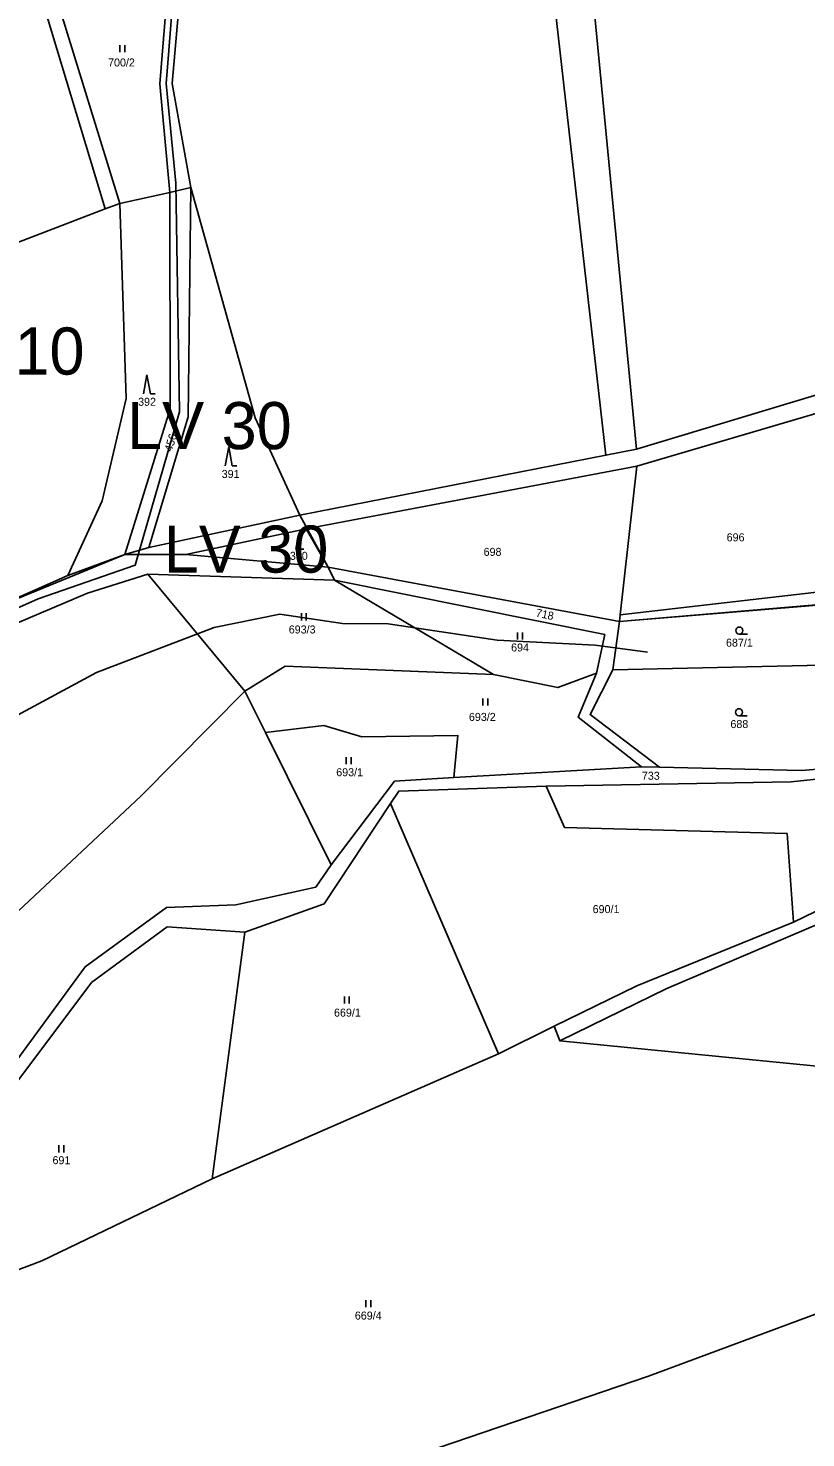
# Model space of a CAD drawing. Extents: x -590606 to -587796, y -1065936 to -1062515.
# Drawn here: x -589979.7 to -589814.6, y -1064835.5 to -1064536.2 of the extents above; entities that cross this region are included whole.
import ezdxf

# ---------------------------------------------------------------- set-up
doc = ezdxf.new("R2010")
doc.units = 0
for name, color, linetype in [('Cesty', 7, 'Continuous'), ('Lesy', 7, 'Continuous'), ('Parcela nároku', 7, 'Continuous'), ('Plocha pro ocenění', 7, 'Continuous'), ('Tok', 7, 'Continuous'), ('Vnější obvod_ Studené', 7, 'Continuous'), ('Vrstva 30', 7, 'Continuous'), ('Čísla LV', 7, 'Continuous')]:
    doc.layers.add(name, color=color, linetype=linetype)

msp = doc.modelspace()

# ---------------------------------------------------------------- linework, layer by layer
at = {"layer": 'Cesty'}
msp.add_lwpolyline([(-589947.72, -1064513.59), (-589949.88, -1064540.92), (-589950.43, -1064547.89), (-589948.41, -1064569.06), (-589947.59, -1064617.66), (-589957.04, -1064650.23), (-589977.62, -1064657.4), (-589994.52, -1064664.89), (-590000.93, -1064670.22), (-590029.62, -1064701.27), (-590052.7, -1064729.41), (-590072.54, -1064740.91), (-590082.04, -1064743), (-590136.41, -1064743.6)], dxfattribs=at)
at = {"layer": 'Lesy'}
for points in [[(-589945.2, -1064570.03), (-589931.51, -1064618.95), (-589922.06, -1064639.58), (-589954.11, -1064646.46), (-589945.75, -1064618.69)], [(-589946.23, -1064647.93), (-589920.74, -1064642.49), (-589916.03, -1064650.62)]]:
    msp.add_lwpolyline(points, close=True, dxfattribs=at)
at = {"layer": 'Parcela nároku'}
for points in [[(-589880.45, -1064400.57), (-589883.7, -1064393.06), (-589937.59, -1064438.88), (-590003.8, -1064511.09), (-590053.49, -1064555.03), (-590124.11, -1064592.68), (-590124.92, -1064590.99), (-590186.83, -1064622.39), (-590180.83, -1064633.16), (-590150.37, -1064687.39), (-590126.23, -1064681.5), (-590102.55, -1064674.49), (-590052.75, -1064654.76), (-590044.76, -1064645), (-590019.81, -1064609.39), (-590007.04, -1064591.31), (-589963.4, -1064574.51), (-589977.74, -1064526.91), (-589976.91, -1064516.68), (-589967.81, -1064501.82), (-589959.93, -1064493.53), (-589948.84, -1064472.81), (-589924.19, -1064439.77), (-589897.81, -1064414.93)], [(-589967.81, -1064501.82), (-589959.93, -1064493.53), (-589948.84, -1064472.81), (-589924.19, -1064439.77), (-589897.81, -1064414.93), (-589880.45, -1064400.57), (-589906.36, -1064425.79), (-589923.6, -1064442.15), (-589947.44, -1064475.52), (-589957.82, -1064495.76), (-589967.27, -1064504.99), (-589974.01, -1064517.56), (-589974.3, -1064527.88), (-589960.29, -1064573.39), (-589963.4, -1064574.51), (-589977.74, -1064526.91), (-589976.91, -1064516.68)], [(-589926.55, -1064452.59), (-589940.54, -1064479.13), (-589948.85, -1064511.85), (-589950.26, -1064528.81), (-589951.76, -1064548.03), (-589949.66, -1064571.06), (-589945.2, -1064570.03), (-589949.14, -1064547.91), (-589946.2, -1064514.04), (-589938.56, -1064481.34), (-589924.47, -1064455.4), (-589901.32, -1064431.9), (-589880.8, -1064419.92), (-589872.2, -1064414.96), (-589874.07, -1064412.43), (-589903.34, -1064429.38)], [(-589859.55, -1064532.21), (-589850.56, -1064625.55), (-589857.07, -1064626.89), (-589868.73, -1064524.47), (-589880.8, -1064419.92), (-589872.2, -1064414.96), (-589869.39, -1064418.76), (-589870.68, -1064462.95), (-589866.7, -1064505.87)], [(-589857.07, -1064626.89), (-589868.73, -1064524.47), (-589880.8, -1064419.92), (-589901.32, -1064431.9), (-589924.47, -1064455.4), (-589938.56, -1064481.34), (-589946.2, -1064514.04), (-589949.14, -1064547.91), (-589945.2, -1064570.03), (-589931.51, -1064618.95), (-589922.06, -1064639.58)], [(-589813.71, -1064476.97), (-589812.63, -1064521.48), (-589808.25, -1064610.3), (-589808.34, -1064612.83), (-589850.56, -1064625.55), (-589859.55, -1064532.21), (-589866.7, -1064505.87), (-589870.68, -1064462.95), (-589869.39, -1064418.76), (-589851.16, -1064443.43), (-589836.69, -1064459.05), (-589820.49, -1064473.59)], [(-589951.76, -1064548.03), (-589949.66, -1064571.06), (-589960.29, -1064573.39), (-589974.3, -1064527.88), (-589950.26, -1064528.81)], [(-589949.56, -1064617.03), (-589959.2, -1064647.94), (-589954.11, -1064646.46), (-589945.75, -1064618.69), (-589945.2, -1064570.03), (-589949.66, -1064571.06)], [(-589922.06, -1064639.58), (-589931.51, -1064618.95), (-589945.2, -1064570.03), (-589945.75, -1064618.69), (-589954.11, -1064646.46)], [(-589964.01, -1064636.55), (-589958.96, -1064614.81), (-589960.29, -1064573.39), (-589949.66, -1064571.06), (-589949.56, -1064617.03), (-589959.2, -1064647.94), (-589971.3, -1064652.42)], [(-589958.96, -1064614.81), (-589960.29, -1064573.39), (-589963.4, -1064574.51), (-590007.04, -1064591.31), (-590019.81, -1064609.39), (-589987.38, -1064659.47), (-589971.3, -1064652.42), (-589964.01, -1064636.55)], [(-589812.35, -1064637.06), (-589807.43, -1064655.35), (-589854.05, -1064660.75), (-589850.49, -1064629.2), (-589810.83, -1064617.52)], [(-589920.74, -1064642.49), (-589850.49, -1064629.2), (-589854.05, -1064660.75), (-589854.21, -1064662.15), (-589916.03, -1064650.62)], [(-589920.74, -1064642.49), (-589946.23, -1064647.93), (-589916.03, -1064650.62)], [(-589854.21, -1064662.15), (-589916.03, -1064650.62), (-589914.7, -1064653.41), (-589857.33, -1064664.94), (-589859.04, -1064673.14), (-589862.93, -1064682.5), (-589849.55, -1064693.06), (-589845.68, -1064693.13), (-589860.43, -1064681.93), (-589855.58, -1064672.44)], [(-590029.38, -1064789.34), (-590030.32, -1064781.93), (-590026.74, -1064766.14), (-590014.61, -1064753.36), (-589994.33, -1064735.3), (-589955.82, -1064699.26), (-589933.74, -1064676.94), (-589954.36, -1064652.15), (-589967.17, -1064656.15), (-589994.87, -1064667.89), (-590049.73, -1064728.85)], [(-589880.93, -1064673.46), (-589914.7, -1064653.41), (-589954.36, -1064652.15), (-589933.74, -1064676.94), (-589925.19, -1064671.68)], [(-589914.7, -1064653.41), (-589857.33, -1064664.94), (-589859.04, -1064673.14), (-589867.3, -1064676.2), (-589880.93, -1064673.46)], [(-589807.43, -1064655.35), (-589854.05, -1064660.75), (-589854.21, -1064662.15), (-589806.62, -1064658.16), (-589803.11, -1064657.97), (-589803.58, -1064654.81)], [(-589855.58, -1064672.44), (-589854.21, -1064662.15), (-589806.62, -1064658.16), (-589803.11, -1064657.97), (-589802.35, -1064663.1), (-589801.71, -1064671.23)], [(-589925.19, -1064671.68), (-589880.93, -1064673.46), (-589867.3, -1064676.2), (-589859.04, -1064673.14), (-589862.93, -1064682.5), (-589849.55, -1064693.06), (-589889.38, -1064695.34), (-589888.53, -1064686.36), (-589908.88, -1064686.7), (-589916.94, -1064684.24), (-589929.38, -1064685.74), (-589933.74, -1064676.94)], [(-589801.89, -1064684.29), (-589800.98, -1064692.6), (-589815.56, -1064693.85), (-589845.68, -1064693.13), (-589860.43, -1064681.93), (-589855.58, -1064672.44), (-589801.71, -1064671.23), (-589801.6, -1064672.57)], [(-589955.82, -1064699.26), (-589933.74, -1064676.94), (-589929.38, -1064685.74), (-589915.44, -1064713.86), (-589918.67, -1064718.62), (-589935.64, -1064722.32), (-589950.4, -1064722.88), (-589967.67, -1064735.51), (-589996.74, -1064775.17), (-590014.61, -1064753.36), (-589994.33, -1064735.3)], [(-589908.88, -1064686.7), (-589916.94, -1064684.24), (-589929.38, -1064685.74), (-589915.44, -1064713.86), (-589901.96, -1064696.06), (-589889.38, -1064695.34), (-589888.53, -1064686.36)], [(-589759.39, -1064687.91), (-589783.04, -1064692.55), (-589817.72, -1064696.23), (-589869.78, -1064697.18), (-589865.85, -1064705.92), (-589818.62, -1064707.21), (-589817.25, -1064726.04), (-589762.08, -1064699.26)], [(-589762.08, -1064699.26), (-589817.25, -1064726.04), (-589850.49, -1064739.56), (-589868.03, -1064748.13), (-589866.87, -1064751.2), (-589844.17, -1064740.14), (-589796.41, -1064719.77), (-589777.67, -1064709.79), (-589759.62, -1064700.86), (-589757.03, -1064687.42), (-589759.39, -1064687.91)], [(-589680.26, -1064689.83), (-589650.2, -1064705.57), (-589660.64, -1064716.31), (-589690.55, -1064743.96), (-589713.8, -1064760.35), (-589721.04, -1064765.62), (-589866.87, -1064751.2), (-589844.17, -1064740.14), (-589796.41, -1064719.77), (-589777.67, -1064709.79), (-589778.73, -1064718.01), (-589723.58, -1064702.36), (-589724.05, -1064691.59)], [(-589818.62, -1064707.21), (-589865.85, -1064705.92), (-589869.78, -1064697.18), (-589901.07, -1064698.2), (-589902.82, -1064700.84), (-589879.87, -1064753.99), (-589868.03, -1064748.13), (-589850.49, -1064739.56), (-589817.25, -1064726.04)], [(-589902.82, -1064700.84), (-589916.87, -1064722.12), (-589933.73, -1064728.16), (-589940.65, -1064780.54), (-589879.87, -1064753.99)], [(-589933.73, -1064728.16), (-589950.22, -1064726.99), (-589966.31, -1064738.85), (-590001.3, -1064785.51), (-590019.97, -1064800.95), (-590021.33, -1064814.7), (-589976.81, -1064797.92), (-589940.65, -1064780.54)], [(-589879.87, -1064753.99), (-589868.03, -1064748.13), (-589866.87, -1064751.2), (-589721.04, -1064765.62), (-589732.48, -1064773.33), (-589781.14, -1064797.6), (-589848.05, -1064822.46), (-589965.99, -1064862.62), (-590008.01, -1064872.65), (-590021.45, -1064817.05), (-590021.33, -1064814.7), (-589976.81, -1064797.92), (-589940.65, -1064780.54)], [(-589848.05, -1064822.46), (-589781.14, -1064797.6), (-589732.48, -1064773.33), (-589721.04, -1064765.62), (-589713.8, -1064760.35), (-589694.16, -1064785.11), (-589709.51, -1064796.54), (-589749.8, -1064818.94), (-589790.83, -1064834.34), (-589885.81, -1064873.92), (-589959.21, -1064893.84), (-589981.68, -1064896.99), (-590005.25, -1064904.42), (-590008.77, -1064887.64), (-590008.01, -1064872.65), (-589965.99, -1064862.62)]]:
    msp.add_lwpolyline(points, close=True, dxfattribs=at)
for points in [[(-589810.83, -1064617.52), (-589850.49, -1064629.2), (-589920.74, -1064642.49), (-589946.23, -1064647.93), (-589959.2, -1064647.94), (-589954.11, -1064646.46), (-589922.06, -1064639.58), (-589857.07, -1064626.89), (-589850.56, -1064625.55), (-589808.34, -1064612.83)], [(-590181.82, -1064746.41), (-590124.93, -1064744.61), (-590077.63, -1064740.78), (-590055.66, -1064729.15), (-590015.95, -1064684.62), (-589998.08, -1064664.3), (-589987.38, -1064659.47), (-589971.3, -1064652.42), (-589959.2, -1064647.94), (-589946.23, -1064647.93), (-589916.03, -1064650.62), (-589914.7, -1064653.41), (-589954.36, -1064652.15), (-589967.17, -1064656.15), (-589994.87, -1064667.89), (-590049.73, -1064728.85), (-590052.18, -1064731.26), (-590075.63, -1064745.31), (-590085.05, -1064746.07), (-590098.16, -1064746.6), (-590102.62, -1064746.78), (-590180.2, -1064750.31)], [(-590001.3, -1064785.51), (-589966.31, -1064738.85), (-589950.22, -1064726.99), (-589933.73, -1064728.16), (-589916.87, -1064722.12), (-589902.82, -1064700.84), (-589901.07, -1064698.2), (-589869.78, -1064697.18), (-589817.72, -1064696.23), (-589783.04, -1064692.55)], [(-589800.98, -1064692.6), (-589815.56, -1064693.85), (-589845.68, -1064693.13), (-589849.55, -1064693.06), (-589889.38, -1064695.34), (-589901.96, -1064696.06), (-589915.44, -1064713.86), (-589918.67, -1064718.62), (-589935.64, -1064722.32), (-589950.4, -1064722.88), (-589967.67, -1064735.51), (-589996.74, -1064775.17)]]:
    msp.add_lwpolyline(points, dxfattribs=at)
at = {"layer": 'Plocha pro ocenění'}
msp.add_lwpolyline([(-590150.37, -1064687.39), (-590126.23, -1064681.5), (-590052.75, -1064654.76), (-590044.76, -1064645), (-590019.81, -1064609.39), (-590007.04, -1064591.31), (-589963.4, -1064574.51), (-589960.29, -1064573.39), (-589949.66, -1064571.06), (-589945.2, -1064570.03), (-589931.51, -1064618.95), (-589922.06, -1064639.58), (-589916.03, -1064650.62), (-589946.23, -1064647.93), (-589959.2, -1064647.94), (-589987.38, -1064659.47), (-589998.08, -1064664.3), (-590015.95, -1064684.62), (-590055.66, -1064729.15), (-590077.63, -1064740.78), (-590124.93, -1064744.61), (-590181.82, -1064746.41)], dxfattribs=at)
at = {"layer": 'Tok'}
msp.add_lwpolyline([(-590084.72, -1064783.05), (-590077.11, -1064778.41), (-590072.98, -1064774.07), (-590066.09, -1064761.92), (-590059.84, -1064752.71), (-590048.45, -1064746.26), (-590037.45, -1064742.42), (-590002.84, -1064725.01), (-589997.1, -1064719.03), (-589997.81, -1064701.47), (-589993.45, -1064692.75), (-589982.91, -1064682.57), (-589965.22, -1064673), (-589940.27, -1064663.42), (-589926.34, -1064660.64), (-589913.01, -1064662.58), (-589903.32, -1064662.68), (-589880.13, -1064666.14), (-589859.37, -1064667.18), (-589848.22, -1064668.7)], dxfattribs=at)
at = {"layer": 'Vnější obvod_ Studené'}
for p, q in [((-589854.21, -1064662.15), (-589803.11, -1064657.97)), ((-589855.58, -1064672.44), (-589854.21, -1064662.15)), ((-589860.43, -1064681.93), (-589855.58, -1064672.44)), ((-589845.68, -1064693.13), (-589860.43, -1064681.93)), ((-589800.98, -1064692.6), (-589815.56, -1064693.85)), ((-589815.56, -1064693.85), (-589845.68, -1064693.13))]:
    msp.add_line(p, q, dxfattribs=at)
at = {"layer": 'Vrstva 30'}
for p, q in [((-589960.25, -1064539.77), (-589960.25, -1064541.27)), ((-589959.22, -1064541.27), (-589959.22, -1064539.77)), ((-589954.52, -1064609.82), (-589955.26, -1064613.82)), ((-589954.52, -1064609.82), (-589953.79, -1064613.82)), ((-589953.79, -1064613.82), (-589952.79, -1064613.82)), ((-589937.15, -1064625.09), (-589937.89, -1064629.09)), ((-589937.15, -1064625.09), (-589936.42, -1064629.09)), ((-589936.42, -1064629.09), (-589935.42, -1064629.09)), ((-589922.39, -1064644.13), (-589922.89, -1064646.81)), ((-589922.39, -1064644.13), (-589921.9, -1064646.81)), ((-589921.9, -1064646.81), (-589921.23, -1064646.81)), ((-589921.73, -1064660.44), (-589921.73, -1064661.94)), ((-589920.7, -1064661.94), (-589920.7, -1064660.44)), ((-589875.82, -1064664.53), (-589875.82, -1064666.03)), ((-589874.8, -1064666.03), (-589874.8, -1064664.53)), ((-589827, -1064664.85), (-589828.75, -1064664.85)), ((-589883.19, -1064678.54), (-589883.19, -1064680.04)), ((-589882.17, -1064680.04), (-589882.17, -1064678.54)), ((-589827.06, -1064682.19), (-589828.81, -1064682.19)), ((-589912.21, -1064691), (-589912.21, -1064692.5)), ((-589911.19, -1064692.5), (-589911.19, -1064691)), ((-589912.58, -1064741.81), (-589912.58, -1064743.31)), ((-589911.56, -1064743.31), (-589911.56, -1064741.81)), ((-589973.22, -1064773.42), (-589973.22, -1064774.92)), ((-589972.2, -1064774.92), (-589972.2, -1064773.42)), ((-589908.03, -1064806.27), (-589908.03, -1064807.77)), ((-589907.01, -1064807.77), (-589907.01, -1064806.27))]:
    msp.add_line(p, q, dxfattribs=at)
for centre in [(-589828.75, -1064664.1), (-589828.81, -1064681.44)]:
    msp.add_circle(centre, 0.75, dxfattribs=at)

# ---------------------------------------------------------------- texts
at = {"layer": 'Parcela nároku'}
for s, p in [('700/2', (-589962.77, -1064544.31)), ('392', (-589956.4, -1064616.37)), ('391', (-589938.65, -1064631.7)), ('696', (-589831.44, -1064645.15)), ('390', (-589924.18, -1064649.08)), ('698', (-589883.04, -1064648.24)), ('693/3', (-589924.41, -1064664.72)), ('687/1', (-589831.58, -1064667.53)), ('694', (-589877.2, -1064668.54)), ('693/2', (-589886.16, -1064683.29)), ('688', (-589830.64, -1064684.81)), ('693/1', (-589914.33, -1064695.04)), ('733', (-589849.44, -1064695.79)), ('690/1', (-589859.89, -1064724.11)), ('669/1', (-589914.8, -1064746.09)), ('691', (-589974.57, -1064777.43)), ('669/4', (-589910.38, -1064810.43))]:
    msp.add_text(s, height=1.7, dxfattribs=at).set_placement(p)
for s, rotation, p in [('456', 72.8298, (-589949.24, -1064626.22)), ('718', 347.8331, (-589872.06, -1064661.1))]:
    msp.add_text(s, height=1.7, rotation=rotation, dxfattribs=at).set_placement(p)
at = {"layer": 'Čísla LV'}
for s, p in [('LV 10', (-590002.72, -1064609.74)), ('LV 30', (-589958.73, -1064625.58)), ('LV 30', (-589950.95, -1064651.8))]:
    msp.add_text(s, height=10, dxfattribs=at).set_placement(p)

doc.saveas('drawing.dxf')
